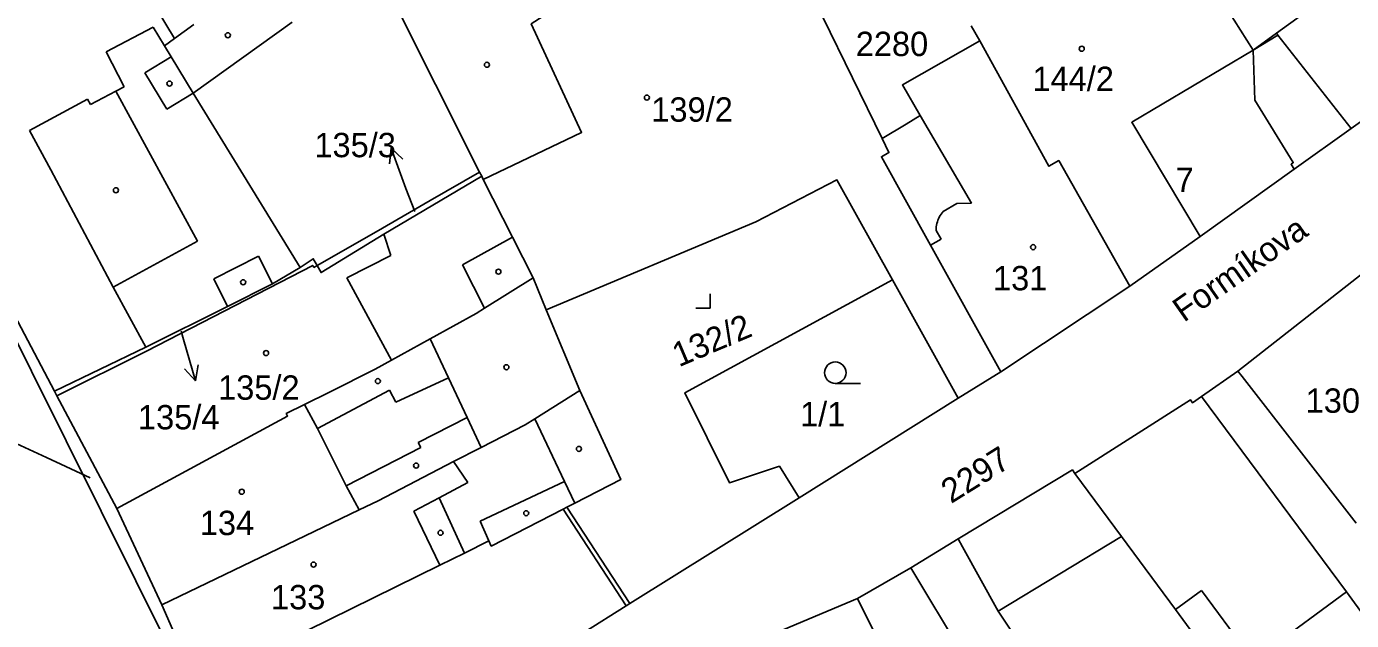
# Model space of a CAD drawing. Extents: x -679220 to -673243, y -1075091 to -1066557.
# Drawn here: x -676340.7 to -676248.3, y -1071784.7 to -1071743.2 of the extents above; entities that cross this region are included whole.
import ezdxf

# ---------------------------------------------------------------- set-up
doc = ezdxf.new("R2010")
doc.units = 0
for name, color, linetype in [('Hranice parcel', 7, 'Continuous'), ('Parcelní čísla', 7, 'Continuous'), ('Pop  PČ popisy', 7, 'Continuous'), ('Vnitřní kresba', 7, 'Continuous'), ('Značky budov', 7, 'Continuous'), ('Značky kultur', 7, 'Continuous')]:
    doc.layers.add(name, color=color, linetype=linetype)

msp = doc.modelspace()

# ---------------------------------------------------------------- linework, layer by layer
at = {"layer": 'Hranice parcel'}
for p, q in [((-676325.68, -1071796.83), (-676359.43, -1071729.07)), ((-676309.12, -1071753.4), (-676315.34, -1071741.03)), ((-676274.81, -1071743.18), (-676274.22, -1071744.24)), ((-676312.57, -1071755.39), (-676309.12, -1071753.4)), ((-676308.97, -1071753.69), (-676309.12, -1071753.4)), ((-676308.86, -1071753.91), (-676308.97, -1071753.69)), ((-676258.85, -1071757.9), (-676252.29, -1071753.19)), ((-676316.34, -1071757.56), (-676312.57, -1071755.39)), ((-676320.46, -1071759.92), (-676316.34, -1071757.56)), ((-676263.74, -1071761.36), (-676258.85, -1071757.9)), ((-676320.46, -1071759.92), (-676320.68, -1071760.05)), ((-676304.47, -1071763.01), (-676305.39, -1071760.79)), ((-676280.3, -1071760.93), (-676275.72, -1071769.19)), ((-676272.75, -1071767.33), (-676263.74, -1071761.36)), ((-676304.47, -1071763.01), (-676302.13, -1071768.64)), ((-676332.37, -1071765.9), (-676338.62, -1071769.01)), ((-676275.72, -1071769.19), (-676272.75, -1071767.33)), ((-676338.79, -1071768.68), (-676338.62, -1071769.01)), ((-676338.62, -1071769.01), (-676334.43, -1071776.89)), ((-676286.82, -1071776.13), (-676275.72, -1071769.19)), ((-676264.34, -1071778.83), (-676267.58, -1071774.43)), ((-676334.43, -1071776.89), (-676331.29, -1071783.6)), ((-676298.64, -1071783.52), (-676303.03, -1071776.79)), ((-676298.64, -1071783.52), (-676286.82, -1071776.13)), ((-676279.03, -1071781.02), (-676282.75, -1071783.17)), ((-676331.29, -1071783.6), (-676328.84, -1071789.2))]:
    msp.add_line(p, q, dxfattribs=at)
for points in [[(-676322.2, -1071742.93), (-676329.1, -1071747.9), (-676330.64, -1071745.35), (-676331.1, -1071744.58), (-676330.4, -1071744.07), (-676334.1, -1071737.92), (-676334.77, -1071736.82), (-676334.99, -1071736.94), (-676344.43, -1071721.33)], [(-676358.95, -1071728.85), (-676358.78, -1071729.17), (-676348.35, -1071750.57), (-676338.79, -1071768.68)], [(-676255.14, -1071744.89), (-676253.41, -1071743.85), (-676253.52, -1071743.71), (-676249.84, -1071741.03), (-676253.06, -1071736.28), (-676254.41, -1071734.37), (-676248.28, -1071730.58), (-676248.09, -1071730.87)], [(-676281.04, -1071751.05), (-676287.23, -1071738.33), (-676284.49, -1071736.87)], [(-676255.14, -1071744.89), (-676258.24, -1071739.97), (-676259.59, -1071737.83)], [(-676308.86, -1071753.91), (-676302, -1071750.63), (-676305.51, -1071743.05), (-676305.26, -1071742.89), (-676300.47, -1071739.8), (-676299.12, -1071738.94)], [(-676274.22, -1071744.24), (-676279.62, -1071747.31), (-676278.38, -1071749.44), (-676279.36, -1071750.06), (-676281.04, -1071751.05)], [(-676263.74, -1071761.36), (-676268.71, -1071752.6), (-676269.4, -1071752.99), (-676274.22, -1071744.24)], [(-676252.29, -1071753.19), (-676248.31, -1071750.35), (-676239.47, -1071744.06)], [(-676258.85, -1071757.9), (-676263.61, -1071749.92), (-676255.14, -1071744.89)], [(-676255.14, -1071744.89), (-676255.03, -1071748.38), (-676252.34, -1071752.74), (-676252.5, -1071752.85), (-676252.29, -1071753.19)], [(-676281.04, -1071751.05), (-676280.56, -1071752.04), (-676281.08, -1071752.33), (-676277.65, -1071758.51), (-676272.75, -1071767.33)], [(-676308.97, -1071753.69), (-676315.81, -1071757.72), (-676320.18, -1071760.41), (-676320.46, -1071759.92)], [(-676305.39, -1071760.79), (-676306.83, -1071757.93), (-676308.86, -1071753.91)], [(-676280.3, -1071760.93), (-676284.19, -1071753.94), (-676289.85, -1071756.87), (-676304.47, -1071763.01)], [(-676338.79, -1071768.68), (-676332.4, -1071765.61), (-676326.7, -1071762.77), (-676323.57, -1071761.19), (-676321.64, -1071760.07), (-676320.73, -1071759.45), (-676320.46, -1071759.92)], [(-676320.68, -1071760.05), (-676320.76, -1071759.91), (-676332.37, -1071765.9)], [(-676246.53, -1071759.72), (-676256.21, -1071767.29), (-676258.74, -1071769.07)], [(-676334.43, -1071776.89), (-676322.52, -1071770.43), (-676322.61, -1071770.25), (-676321.33, -1071769.61), (-676319.59, -1071768.75), (-676316.41, -1071767.16), (-676315.27, -1071766.53), (-676312.56, -1071765.03), (-676309.37, -1071763.27), (-676308.77, -1071762.9), (-676305.39, -1071760.79)], [(-676286.82, -1071776.13), (-676288.2, -1071773.93), (-676291.69, -1071775.08), (-676294.81, -1071768.81), (-676280.3, -1071760.93)], [(-676302.13, -1071768.64), (-676305.27, -1071770.62), (-676305.94, -1071771.05), (-676309.01, -1071772.62), (-676310.93, -1071773.6), (-676316.2, -1071776.34), (-676317.53, -1071776.98), (-676331.29, -1071783.6)], [(-676302.13, -1071768.64), (-676299.26, -1071774.85), (-676302.48, -1071776.51), (-676303.03, -1071776.79)], [(-676258.74, -1071769.07), (-676259.37, -1071769.51), (-676259.51, -1071769.3), (-676267.58, -1071774.43)], [(-676258.74, -1071769.07), (-676248.63, -1071782.69), (-676246.06, -1071786.2)], [(-676267.58, -1071774.43), (-676267.76, -1071774.19), (-676275.72, -1071779.01), (-676279.03, -1071781.02)], [(-676303.03, -1071776.79), (-676303.3, -1071776.93), (-676308.31, -1071779.5), (-676308.48, -1071779.14), (-676310.18, -1071779.99), (-676311.9, -1071780.84), (-676328.84, -1071789.2)], [(-676254.83, -1071791.71), (-676263.35, -1071798.44), (-676272.94, -1071784.05), (-676264.34, -1071778.83)], [(-676264.34, -1071778.83), (-676260.56, -1071783.93), (-676256.83, -1071789), (-676254.83, -1071791.71)], [(-676279.03, -1071781.02), (-676275.42, -1071787.02), (-676272.85, -1071791.32)], [(-676282.75, -1071783.17), (-676289.65, -1071786.08), (-676298.28, -1071789.88)], [(-676282.75, -1071783.17), (-676279.54, -1071789.64), (-676280.11, -1071791.32), (-676282.53, -1071793.01)], [(-676325.68, -1071796.83), (-676304.75, -1071787.77), (-676304.9, -1071787.5), (-676301.73, -1071785.74), (-676301.85, -1071785.53), (-676298.89, -1071783.68), (-676298.64, -1071783.52)]]:
    msp.add_lwpolyline(points, dxfattribs=at)
at = {"layer": 'Pop  PČ popisy'}
for p, q in [((-676315.286, -1071751.72), (-676315.414, -1071752.832)), ((-676314.26, -1071754.54), (-676315.286, -1071751.72)), ((-676315.286, -1071751.72), (-676314.473, -1071752.49)), ((-676313.65, -1071756.16), (-676314.26, -1071754.54)), ((-676329.94, -1071764.5), (-676329.78, -1071765.08)), ((-676329.78, -1071765.08), (-676328.953, -1071767.965)), ((-676328.953, -1071767.965), (-676329.71, -1071767.14)), ((-676328.953, -1071767.965), (-676328.748, -1071766.864)), ((-676339.35, -1071773.33), (-676342.07, -1071772.062)), ((-676336.3, -1071774.74), (-676339.35, -1071773.33))]:
    msp.add_line(p, q, dxfattribs=at)
at = {"layer": 'Vnitřní kresba'}
for p, q in [((-676335.18, -1071745), (-676331.9, -1071743.29)), ((-676331.9, -1071743.29), (-676331.1, -1071744.58)), ((-676330.4, -1071744.07), (-676329.05, -1071743.1)), ((-676255.14, -1071744.89), (-676253.52, -1071743.71)), ((-676248.31, -1071750.35), (-676253.41, -1071743.85)), ((-676333.91, -1071747.44), (-676335.18, -1071745)), ((-676330.64, -1071745.35), (-676332.48, -1071746.46)), ((-676332.48, -1071746.46), (-676330.94, -1071749.01)), ((-676336.27, -1071748.68), (-676334.51, -1071747.75)), ((-676334.51, -1071747.75), (-676333.91, -1071747.44)), ((-676334.51, -1071747.75), (-676328.8, -1071758.22)), ((-676330.94, -1071749.01), (-676329.1, -1071747.9)), ((-676329.1, -1071747.9), (-676321.64, -1071760.07)), ((-676340.52, -1071750.49), (-676336.47, -1071748.31)), ((-676336.47, -1071748.31), (-676336.27, -1071748.68)), ((-676278.38, -1071749.44), (-676274.79, -1071755.57)), ((-676339.04, -1071753.25), (-676340.52, -1071750.49)), ((-676334.69, -1071761.43), (-676339.04, -1071753.25)), ((-676276.78, -1071756.14), (-676275.82, -1071755.58)), ((-676274.79, -1071755.57), (-676275.82, -1071755.58)), ((-676276.92, -1071758.08), (-676277.27, -1071757.47)), ((-676328.8, -1071758.22), (-676334.69, -1071761.43)), ((-676315.31, -1071759.22), (-676315.81, -1071757.72)), ((-676310.31, -1071759.87), (-676306.83, -1071757.93)), ((-676277.65, -1071758.51), (-676276.92, -1071758.08)), ((-676327.67, -1071760.86), (-676324.54, -1071759.27)), ((-676324.54, -1071759.27), (-676323.57, -1071761.19)), ((-676318.38, -1071760.77), (-676315.31, -1071759.22)), ((-676308.77, -1071762.9), (-676310.31, -1071759.87)), ((-676326.7, -1071762.77), (-676327.67, -1071760.86)), ((-676318.38, -1071760.77), (-676315.27, -1071766.53)), ((-676332.4, -1071765.61), (-676334.69, -1071761.43)), ((-676312.56, -1071765.03), (-676311.29, -1071767.75)), ((-676256.21, -1071767.29), (-676255.92, -1071767.67)), ((-676255.92, -1071767.67), (-676247.96, -1071777.91)), ((-676320.44, -1071771.29), (-676315.41, -1071768.62)), ((-676315.41, -1071768.62), (-676314.96, -1071769.46)), ((-676314.96, -1071769.46), (-676311.29, -1071767.75)), ((-676311.29, -1071767.75), (-676309.99, -1071770.53)), ((-676321.33, -1071769.61), (-676320.44, -1071771.29)), ((-676320.44, -1071771.29), (-676318.43, -1071775.29)), ((-676313.4, -1071772.27), (-676309.99, -1071770.53)), ((-676309.99, -1071770.53), (-676309.01, -1071772.62)), ((-676303.2, -1071774.99), (-676305.27, -1071770.62)), ((-676313.22, -1071772.63), (-676313.4, -1071772.27)), ((-676318.43, -1071775.29), (-676313.22, -1071772.63)), ((-676310.93, -1071773.6), (-676309.95, -1071775.07)), ((-676311.94, -1071776.13), (-676309.95, -1071775.07)), ((-676309.08, -1071777.76), (-676303.2, -1071774.99)), ((-676302.48, -1071776.51), (-676303.2, -1071774.99)), ((-676318.43, -1071775.29), (-676317.53, -1071776.98)), ((-676313.7, -1071777.06), (-676311.94, -1071776.13)), ((-676311.94, -1071776.13), (-676310.18, -1071779.99)), ((-676303.3, -1071776.93), (-676298.89, -1071783.68)), ((-676311.9, -1071780.84), (-676313.7, -1071777.06)), ((-676308.48, -1071779.14), (-676309.08, -1071777.76)), ((-676275.72, -1071779.01), (-676275.42, -1071779.56)), ((-676275.42, -1071779.56), (-676272.94, -1071784.05)), ((-676260.56, -1071783.93), (-676258.75, -1071782.6)), ((-676258.75, -1071782.6), (-676255.14, -1071787.49)), ((-676255.14, -1071787.49), (-676248.63, -1071782.69))]:
    msp.add_line(p, q, dxfattribs=at)
msp.add_lwpolyline([(-676277.27, -1071757.47), (-676277.265, -1071757.35), (-676277.253, -1071757.23), (-676277.235, -1071757.111), (-676277.209, -1071756.993), (-676277.178, -1071756.877), (-676277.139, -1071756.763), (-676277.094, -1071756.651), (-676277.043, -1071756.542), (-676276.986, -1071756.436), (-676276.923, -1071756.334), (-676276.854, -1071756.235), (-676276.78, -1071756.14)], dxfattribs=at)
at = {"layer": 'Značky budov'}
for centre in [(-676326.687, -1071743.849), (-676267.107, -1071744.789), (-676308.607, -1071745.909), (-676330.757, -1071747.219), (-676297.447, -1071748.199), (-676334.497, -1071754.669), (-676270.497, -1071758.639), (-676307.807, -1071760.349), (-676325.617, -1071761.089), (-676324.017, -1071766.029), (-676307.247, -1071767.019), (-676316.217, -1071767.989), (-676302.187, -1071772.719), (-676313.547, -1071773.889), (-676325.717, -1071775.709), (-676305.867, -1071777.209), (-676311.847, -1071778.579), (-676320.707, -1071780.799)]:
    msp.add_circle(centre, 0.175, dxfattribs=at)
at = {"layer": 'Značky kultur'}
for p, q in [((-676293.04, -1071762.9), (-676293.04, -1071761.9)), ((-676294.041, -1071762.9), (-676293.04, -1071762.9)), ((-676284.303, -1071768.15), (-676282.553, -1071768.15))]:
    msp.add_line(p, q, dxfattribs=at)
msp.add_circle((-676284.303, -1071767.4), 0.75, dxfattribs=at)

# ---------------------------------------------------------------- texts
at = {"layer": 'Parcelní čísla'}
for s, p in [('2280', (-676282.874, -1071745.3)), ('144/2', (-676270.548, -1071747.739)), ('139/2', (-676297.138, -1071749.88)), ('135/3', (-676320.648, -1071752.36)), ('7', (-676260.556, -1071754.79)), ('131', (-676273.295, -1071761.65)), ('135/2', (-676327.368, -1071769.29)), ('130/1', (-676251.478, -1071770.2)), ('1/1', (-676286.76, -1071771.14)), ('135/4', (-676332.958, -1071771.358)), ('134', (-676328.645, -1071778.739)), ('133', (-676323.675, -1071783.92))]:
    msp.add_text(s, height=1.7, dxfattribs=at).set_placement(p)
for s, rotation, p in [('132/2', 23, (-676295.214, -1071767.031)), ('2297', 32, (-676276.221, -1071776.576))]:
    msp.add_text(s, height=1.7, rotation=rotation, dxfattribs=at).set_placement(p)
at = {"layer": 'Pop  PČ popisy'}
msp.add_text('Formíkova', height=1.7, rotation=35, dxfattribs=at).set_placement((-676259.981, -1071763.922))

doc.saveas('drawing.dxf')
